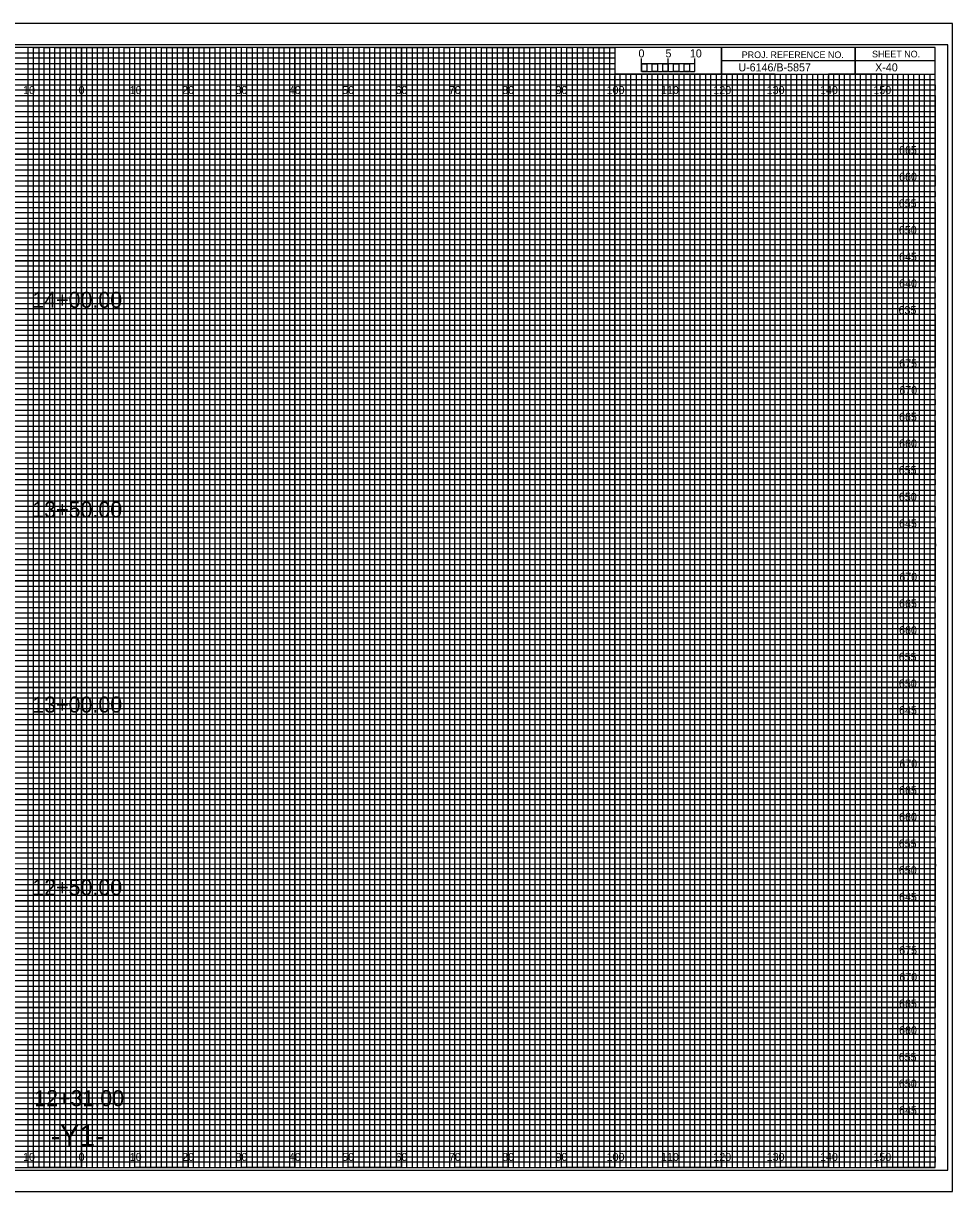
# Model space of a CAD drawing. Extents: x -13 to 323, y 215 to 434.
# Drawn here: x 149.1 to 323.3, y 215.5 to 434.5 of the extents above; entities that cross this region are included whole.
import ezdxf

# ---------------------------------------------------------------- set-up
doc = ezdxf.new("R2010")
doc.units = 0
for name, color, linetype in [('Exist Cross Section Cell', 7, 'Continuous'), ('Exist XS Center Line Elevation Label', 7, 'Continuous'), ('Exist XS Ground Line', 7, 'Continuous'), ('Prop XS Ditch Slope Text', 7, 'Continuous'), ('Prop XS Ditch Standard Text', 7, 'Continuous'), ('Prop XS Dump Level', 7, 'Continuous'), ('Prop XS EOT Tick Mark', 7, 'Continuous'), ('Prop XS Finish Grade', 7, 'Continuous'), ('Prop XS Finish Grade Earthwork', 7, 'Continuous'), ('Prop XS Finish Grade Pavement', 7, 'Continuous'), ('Prop XS Hydro Elevations', 7, 'Continuous'), ('Prop XS Pvmt Edge Slope', 7, 'Continuous'), ('Prop XS SE Text', 7, 'Continuous'), ('Prop XS Side Slope Text', 7, 'Continuous'), ('Prop XS SS Elevation Text', 7, 'Continuous'), ('Prop XS Subgrade Earthwork', 7, 'Continuous'), ('Scratch_Level_3', 7, 'Continuous')]:
    doc.layers.add(name, color=color, linetype=linetype)

msp = doc.modelspace()

# ---------------------------------------------------------------- linework, layer by layer
at = {"layer": 'Exist Cross Section Cell'}
for points in [[(145, 220), (155, 220), (155, 430), (165, 430), (165, 220), (175, 220), (175, 430), (185, 430), (185, 220), (195, 220), (195, 430), (205, 430), (205, 220), (215, 220), (215, 430), (225, 430), (225, 220), (235, 220), (235, 430), (245, 430), (245, 220), (255, 220), (255, 430), (259.93, 430), (260, 430), (260, 425), (264.99, 425), (264.99, 220), (275, 220), (275, 425), (285, 425), (285, 220), (295, 220), (295, 425), (305, 425), (305, 220), (315, 220), (315, 425)], [(0, 425), (275, 425)], [(0, 405), (320, 405), (320, 415), (0, 415)], [(0, 385), (320, 385), (320, 395), (0, 395)], [(0, 365), (320, 365), (320, 375), (0, 375)], [(0, 345), (320, 345), (320, 355), (0, 355)], [(0, 325), (320, 325), (320, 335), (0, 335)], [(0, 305), (320, 305), (320, 315), (0, 315)], [(0, 285), (320, 285), (320, 295), (0, 295)], [(0, 265), (320, 265), (320, 275), (0, 275)], [(0, 245), (320, 245), (320, 255), (0, 255)], [(0, 225), (320, 225), (320, 235), (0, 235)]]:
    msp.add_lwpolyline(points, dxfattribs=at)
at = {"layer": 'Exist XS Center Line Elevation Label'}
for p, q in [((150, 430), (140, 430)), ((150, 220), (150, 430)), ((170, 430), (160, 430)), ((160, 430), (160, 220)), ((170, 220), (170, 430)), ((190, 430), (180, 430)), ((180, 430), (180, 220)), ((190, 220), (190, 430)), ((210, 430), (200, 430)), ((200, 430), (200, 220)), ((210, 220), (210, 430)), ((230, 430), (220, 430)), ((220, 430), (220, 220)), ((230, 220), (230, 430)), ((250, 430), (240, 430)), ((240, 430), (240, 220)), ((250, 220), (250, 430)), ((260, 430), (260, 220)), ((270, 220), (270, 425)), ((290, 425), (280, 425)), ((280, 425), (280, 220)), ((290, 220), (290, 425)), ((310, 425), (300, 425)), ((300, 425), (300, 220)), ((310, 220), (310, 425)), ((160, 220), (150, 220)), ((180, 220), (170, 220)), ((200, 220), (190, 220)), ((220, 220), (210, 220)), ((240, 220), (230, 220)), ((260, 220), (250, 220)), ((280, 220), (270, 220)), ((300, 220), (290, 220)), ((320, 220), (310, 220)), ((320, 220), (320, 220))]:
    msp.add_line(p, q, dxfattribs=at)
for points in [[(0, 420), (320, 420), (320, 410), (0, 410)], [(0, 400), (320, 400), (320, 390), (0, 390)], [(0, 380), (320, 380), (320, 370), (0, 370)], [(0, 360), (320, 360), (320, 350), (0, 350)], [(0, 340), (320, 340), (320, 330), (0, 330)], [(0, 320), (320, 320), (320, 310), (0, 310)], [(0, 300), (320, 300), (320, 290), (0, 290)], [(0, 280), (320, 280), (320, 270), (0, 270)], [(0, 260), (320, 260), (320, 250), (0, 250)], [(0, 240), (320, 240), (320, 230), (0, 230)]]:
    msp.add_lwpolyline(points, dxfattribs=at)
at = {"layer": 'Prop XS Ditch Slope Text'}
msp.add_lwpolyline([(-13.4, 215.5), (323.3, 215.5), (323.3, 434.5), (-13.4, 434.5)], close=True, dxfattribs=at)
at = {"layer": 'Prop XS Ditch Standard Text'}
for p, q in [((265, 425.49), (265, 427.9)), ((265, 426.9), (265, 427.9)), ((270, 425.49), (270, 427.9)), ((275, 425.49), (275, 427.9)), ((275, 426.9), (275, 427.9))]:
    msp.add_line(p, q, dxfattribs=at)
for points in [[(275, 426.9), (265, 426.9), (265, 425.49), (275, 425.49)], [(265, 426.9), (266, 426.9), (266, 425.49), (265, 425.49)], [(267, 426.9), (268, 426.9), (268, 425.49), (267, 425.49)], [(269, 426.9), (270, 426.9), (270, 425.49), (269, 425.49)], [(271, 426.9), (272, 426.9), (272, 425.49), (271, 425.49)], [(273, 426.9), (274, 426.9), (274, 425.49), (273, 425.49)]]:
    msp.add_lwpolyline(points, close=True, dxfattribs=at)
at = {"layer": 'Prop XS Dump Level'}
for p, q in [((305, 430), (305, 425)), ((305, 425), (305, 430)), ((280, 427.5), (280, 425)), ((320, 427.49), (280, 427.49)), ((280, 425), (320, 425))]:
    msp.add_line(p, q, dxfattribs=at)
for points in [[(320, 430), (0, 430), (0, 220), (320, 220)], [(280, 430), (260, 430), (260, 425.03), (280, 425.03)], [(320, 430), (280, 430), (280, 425), (320, 425)]]:
    msp.add_lwpolyline(points, close=True, dxfattribs=at)
at = {"layer": 'Prop XS Finish Grade Earthwork'}
for p, q in [((323.3, 434.5), (-13.4, 434.5)), ((-13.4, 215.5), (323.3, 215.5))]:
    msp.add_line(p, q, dxfattribs=at)
at = {"layer": 'Prop XS SE Text'}
for p, q in [((267, 425), (266.01, 425)), ((266.01, 425), (266.01, 220)), ((267, 220), (267, 425)), ((269, 425), (268, 425)), ((268, 425), (268, 220)), ((269, 220), (269, 425)), ((266.01, 220), (265, 220)), ((268, 220), (267, 220))]:
    msp.add_line(p, q, dxfattribs=at)
for points in [[(150, 220), (151, 220), (151, 430), (152, 430), (152, 220)], [(152, 220), (153, 220), (153, 430), (154, 430), (154, 220)], [(155, 220), (156, 220), (156, 430), (157, 430), (157, 220)], [(157, 220), (158, 220), (158, 430), (159, 430), (159, 220)], [(160, 220), (161, 220), (161, 430), (162, 430), (162, 220)], [(162, 220), (163, 220), (163, 430), (164, 430), (164, 220)], [(165, 220), (166, 220), (166, 430), (167, 430), (167, 220)], [(167, 220), (168, 220), (168, 430), (169, 430), (169, 220)], [(170, 220), (171, 220), (171, 430), (172, 430), (172, 220)], [(172, 220), (173, 220), (173, 430), (174, 430), (174, 220)], [(175, 220), (176, 220), (176, 430), (177, 430), (177, 220)], [(177, 220), (178, 220), (178, 430), (179, 430), (179, 220)], [(180, 220), (181, 220), (181, 430), (182, 430), (182, 220)], [(182, 220), (183, 220), (183, 430), (184, 430), (184, 220)], [(185, 220), (186, 220), (186, 430), (187, 430), (187, 220)], [(187, 220), (188, 220), (188, 430), (189, 430), (189, 220)], [(190, 220), (191, 220), (191, 430), (192, 430), (192, 220)], [(192, 220), (193, 220), (193, 430), (194, 430), (194, 220)], [(195, 220), (196, 220), (196, 430), (197, 430), (197, 220)], [(197, 220), (198, 220), (198, 430), (199, 430), (199, 220)], [(200, 220), (201, 220), (201, 430), (202, 430), (202, 220)], [(202, 220), (203, 220), (203, 430), (204, 430), (204, 220)], [(205, 220), (206, 220), (206, 430), (207, 430), (207, 220)], [(207, 220), (208, 220), (208, 430), (209, 430), (209, 220)], [(210, 220), (211, 220), (211, 430), (212, 430), (212, 220)], [(212, 220), (213, 220), (213, 430), (214, 430), (214, 220)], [(215, 220), (216, 220), (216, 430), (217, 430), (217, 220)], [(217, 220), (218, 220), (218, 430), (219, 430), (219, 220)], [(220, 220), (221, 220), (221, 430), (222, 430), (222, 220)], [(222, 220), (223, 220), (223, 430), (224, 430), (224, 220)], [(225, 220), (226, 220), (226, 430), (227, 430), (227, 220)], [(227, 220), (228, 220), (228, 430), (229, 430), (229, 220)], [(230, 220), (231, 220), (231, 430), (232, 430), (232, 220)], [(232, 220), (233, 220), (233, 430), (234, 430), (234, 220)], [(235, 220), (236, 220), (236, 430), (237, 430), (237, 220)], [(237, 220), (238, 220), (238, 430), (239, 430), (239, 220)], [(240, 220), (241, 220), (241, 430), (242, 430), (242, 220)], [(242, 220), (243, 220), (243, 430), (244, 430), (244, 220)], [(245, 220), (246, 220), (246, 430), (247, 430), (247, 220)], [(247, 220), (248, 220), (248, 430), (249, 430), (249, 220)], [(250, 220), (251, 220), (251, 430), (252, 430), (252, 220)], [(252, 220), (253, 220), (253, 430), (254, 430), (254, 220)], [(255, 220), (256, 220), (256, 430), (257, 430), (257, 220)], [(257, 220), (258, 220), (258, 430), (259, 430), (259, 220)], [(260, 220), (261, 220), (261, 425), (262.02, 425), (262.02, 220)], [(262, 220), (263, 220), (263, 425), (263.99, 425), (263.99, 220)], [(270, 220), (270.98, 220), (270.98, 425), (272, 425), (272, 220)], [(272, 220), (273, 220), (273, 425), (274.05, 425), (274.05, 220)], [(275, 220), (276, 220), (276, 425), (277, 425), (277, 220)], [(277, 220), (278, 220), (278, 425), (279, 425), (279, 220)], [(280, 220), (281, 220), (281, 425), (282, 425), (282, 220)], [(282, 220), (283, 220), (283, 425), (284, 425), (284, 220)], [(285, 220), (286, 220), (286, 425), (287, 425), (287, 220)], [(287, 220), (288, 220), (288, 425), (289, 425), (289, 220)], [(290, 220), (291, 220), (291, 425), (292, 425), (292, 220)], [(292, 220), (293, 220), (293, 425), (294, 425), (294, 220)], [(295, 220), (296, 220), (296, 425), (297, 425), (297, 220)], [(297, 220), (298, 220), (298, 425), (299, 425), (299, 220)], [(300, 220), (301, 220), (301, 425), (302, 425), (302, 220)], [(302, 220), (303, 220), (303, 425), (304, 425), (304, 220)], [(305, 220), (306, 220), (306, 425), (307, 425), (307, 220)], [(307, 220), (308, 220), (308, 425), (309, 425), (309, 220)], [(310, 220), (311, 220), (311, 425), (312, 425), (312, 220)], [(312, 220), (313, 220), (313, 425), (314, 425), (314, 220)], [(315, 220), (316, 220), (316, 425), (317, 425), (317, 220)], [(317, 220), (318, 220), (318, 425), (319, 425), (319, 220)]]:
    msp.add_lwpolyline(points, dxfattribs=at)
at = {"layer": 'Prop XS Side Slope Text'}
msp.add_lwpolyline([(-10.8, 219.5), (322.4, 219.5), (322.4, 430.5), (-10.8, 430.5)], close=True, dxfattribs=at)
at = {"layer": 'Prop XS SS Elevation Text'}
for p, q in [((150, 220), (150, 430)), ((160, 220), (160, 430)), ((170, 220), (170, 430)), ((180, 220), (180, 430)), ((190, 220), (190, 430)), ((200, 220), (200, 430)), ((210, 220), (210, 430)), ((220, 220), (220, 430)), ((230, 220), (230, 430)), ((240, 220), (240, 430)), ((250, 220), (250, 430)), ((260, 220), (260, 424.69)), ((270, 220), (270, 424.69)), ((280, 220), (280, 424.69)), ((290, 220), (290, 424.69)), ((300, 220), (300, 424.69)), ((310, 220), (310, 424.69)), ((0, 420), (320, 420)), ((0, 410), (320, 410)), ((0, 400), (320, 400)), ((0, 390), (320, 390)), ((0, 380), (320, 380)), ((0, 370), (320, 370)), ((0, 360), (320, 360)), ((0, 350), (320, 350)), ((0, 340), (320, 340)), ((0, 330), (320, 330)), ((0, 320), (320, 320)), ((0, 310), (320, 310)), ((0, 300), (320, 300)), ((0, 290), (320, 290)), ((0, 280), (320, 280)), ((0, 270), (320, 270)), ((0, 260), (320, 260)), ((0, 250), (320, 250)), ((0, 240), (320, 240)), ((0, 230), (320, 230))]:
    msp.add_line(p, q, dxfattribs=at)
at = {"layer": 'Scratch_Level_3'}
for p, q in [((0, 429), (260, 429)), ((260, 427.98), (0, 427.98)), ((260, 429), (260, 427.98)), ((0, 427), (260, 427)), ((260, 425.89), (0, 425.89)), ((260, 427), (260, 425.89)), ((0, 424), (320, 424))]:
    msp.add_line(p, q, dxfattribs=at)
for points in [[(0, 423), (270, 423), (320, 423), (320, 422), (0, 422)], [(0, 421), (320, 421), (320, 419), (0, 419)], [(0, 418), (320, 418), (320, 417), (0, 416.98)], [(0, 416), (320, 416), (320, 414), (0, 414)], [(0, 413), (320, 413), (320, 412), (0, 412)], [(0, 411), (320, 411), (320, 409), (0, 409)], [(0, 408), (320, 408), (320, 407), (0, 407)], [(0, 406), (320, 406), (320, 404), (0, 404)], [(0, 403), (320, 403), (320, 402), (0, 402)], [(0, 401), (320, 401), (320, 399), (0, 399)], [(0, 398), (320, 398), (320, 397), (0, 397)], [(0, 396), (320, 396), (320, 393.95), (320, 393), (320, 392), (0, 392)], [(0, 394), (320, 394), (320, 393), (0, 393)], [(0, 391), (320, 391), (320, 389), (0, 389.03)], [(0, 389.03), (320, 389), (320, 388), (0, 388)], [(0, 387), (320, 387), (320, 386), (0, 386)], [(0, 384), (320, 384), (320, 383), (0, 383)], [(0, 382), (320, 382), (320, 381), (0, 381)], [(-0.07, 378.89), (320, 378.89), (320, 377.88), (-0.07, 377.88)], [(0, 377), (320, 377), (320, 376), (0, 376)], [(0, 374), (320, 374), (320, 373), (0, 373)], [(0, 372), (320, 372), (320, 371), (0, 371)], [(0, 369), (320, 369), (320, 368), (0, 368)], [(0, 367), (320, 367), (320, 366), (0, 366)], [(0, 364), (320, 364), (320, 363), (0, 363)], [(0, 362), (320, 362), (320, 361), (0, 361)], [(0, 359), (320, 359), (319.99, 357.98), (0, 358)], [(0, 357), (320, 357), (320, 356), (0, 356)], [(0, 354), (320, 354), (320, 353), (0, 353)], [(0, 352), (320, 352), (320, 351), (0, 351)], [(0, 349), (320, 349), (320, 348), (0, 348)], [(0, 347), (320, 347), (320, 346), (0, 346)], [(0, 344), (320, 344), (320, 343), (0, 343)], [(0, 342), (320, 342), (320, 341), (0, 341)], [(0, 339), (320, 339), (320, 338), (0, 338)], [(0, 336.99), (320.07, 336.91), (320, 336), (0, 336)], [(0, 334), (320, 334), (320, 333), (0, 333)], [(0, 332), (320, 332), (320, 331), (0, 331)], [(0, 329), (320, 329), (320, 328), (0, 328)], [(0, 327), (320, 327), (320, 326), (0, 326)], [(0, 324), (320, 324), (320, 323), (0, 323)], [(0, 322), (320, 322), (320, 321), (0, 321)], [(0, 319), (320, 319), (320, 318), (0, 318)], [(0, 317), (320, 317), (320, 316), (0, 316)], [(0, 314), (320, 314), (320, 313), (0, 313)], [(0, 312), (320, 312), (320, 311), (0, 311)], [(0, 309), (320, 309), (320, 308), (0, 308)], [(0, 307), (320, 307), (320, 306), (0, 306)], [(0, 304), (320, 304), (320, 303), (0, 303)], [(0, 302), (320, 302), (320, 301), (0, 301)], [(0, 299), (320, 299), (319.99, 297.98), (0, 298)], [(0, 297), (320, 297), (320, 296), (0, 296)], [(0, 294), (320, 294), (320, 293), (0, 293)], [(0, 292), (320, 292), (320, 291), (0, 291)], [(0, 289), (320, 289), (320, 288), (0, 288)], [(0, 287), (320, 287), (320, 286), (0, 286)], [(0, 284), (320, 284), (320, 283), (0, 283)], [(0, 282), (320, 282), (320, 281), (0, 281)], [(0, 279), (320, 279), (320, 278), (0, 278)], [(0, 276.99), (320.07, 276.91), (320, 276), (0, 276)], [(0, 274), (320, 274), (320, 273), (0, 273)], [(0, 272), (320, 272), (320, 271), (0, 271)], [(0, 269), (320, 269), (320, 268), (0, 268)], [(0, 267), (320, 267), (320, 266), (0, 266)], [(0, 264), (320, 264), (320, 263), (0, 263)], [(0, 262), (320, 262), (320, 261), (0, 261)], [(0, 259), (320, 259), (320, 258), (0, 258)], [(0, 257), (320, 257), (320, 256), (0, 256)], [(0, 254), (320, 254), (320, 253), (0, 253)], [(0, 252), (320, 252), (320, 251), (0, 251)], [(0, 249), (320, 249), (320, 248), (0, 248)], [(0, 247), (320, 247), (320, 246), (0, 246)], [(0, 244), (320, 244), (320, 243), (0, 243)], [(0, 242), (320, 242), (320, 241), (0, 241)], [(0, 239), (320, 239), (320, 238), (0, 238)], [(0, 237), (320, 237), (320, 236), (0, 236)], [(0, 234), (320, 234), (320, 233), (0, 233)], [(0, 232), (320, 232), (320, 231), (0, 231)], [(0, 229), (320, 229), (320, 228), (0, 228)], [(0, 227), (320, 227), (320, 226), (0, 226)], [(0, 224), (320, 224), (320, 223), (0, 223)], [(0, 222), (320, 222), (320, 221), (0, 221)]]:
    msp.add_lwpolyline(points, dxfattribs=at)

# ---------------------------------------------------------------- texts
at = {"layer": 'Exist XS Ground Line'}
for s, p in [('10', (149.04, 421.25)), ('0', (159.45, 421.25)), ('0', (159.45, 421.25)), ('10', (169.04, 421.25)), ('20', (178.86, 421.25)), ('30', (188.86, 421.25)), ('40', (198.86, 421.25)), ('50', (208.86, 421.25)), ('60', (218.86, 421.25)), ('70', (228.86, 421.25)), ('80', (238.86, 421.25)), ('90', (248.86, 421.25)), ('100', (258.44, 421.25)), ('110', (268.62, 421.25)), ('120', (278.44, 421.25)), ('130', (288.44, 421.25)), ('140', (298.44, 421.25)), ('150', (308.44, 421.25)), ('10', (149.04, 221.25)), ('0', (159.45, 221.25)), ('0', (159.45, 221.25)), ('10', (169.04, 221.25)), ('20', (178.86, 221.25)), ('30', (188.86, 221.25)), ('40', (198.86, 221.25)), ('50', (208.86, 221.25)), ('60', (218.86, 221.25)), ('70', (228.86, 221.25)), ('80', (238.86, 221.25)), ('90', (248.86, 221.25)), ('100', (258.44, 221.25)), ('110', (268.62, 221.25)), ('120', (278.44, 221.25)), ('130', (288.44, 221.25)), ('140', (298.44, 221.25)), ('150', (308.44, 221.25))]:
    msp.add_text(s, height=1.5, dxfattribs=at).set_placement(p)
at = {"layer": 'Prop XS Ditch Standard Text'}
msp.add_text('0', height=1.5, dxfattribs=at).set_placement((264.41, 428.12))
at = {"layer": 'Prop XS Dump Level'}
for s, p in [('PROJ. REFERENCE NO.', (283.77, 427.99)), ('SHEET NO.', (308.19, 428.12))]:
    msp.add_text(s, height=1.25, dxfattribs=at).set_placement(p)
at = {"layer": 'Prop XS EOT Tick Mark'}
msp.add_text('U-6146/B-5857', height=1.5, dxfattribs=at).set_placement((283.13, 425.5))
at = {"layer": 'Prop XS Finish Grade'}
for s, p in [('665', (313.25, 410)), ('660', (313.26, 405)), ('655', (313.2, 400)), ('650', (313.22, 395)), ('645', (313.25, 390)), ('640', (313.26, 385)), ('635', (313.16, 380)), ('675', (313.28, 370)), ('670', (313.3, 365)), ('665', (313.25, 360)), ('660', (313.26, 355)), ('655', (313.2, 350)), ('650', (313.22, 345)), ('645', (313.25, 340)), ('670', (313.3, 330)), ('665', (313.25, 325)), ('660', (313.26, 320)), ('655', (313.2, 315)), ('650', (313.22, 310)), ('645', (313.25, 305)), ('670', (313.3, 295)), ('665', (313.25, 290)), ('660', (313.26, 285)), ('655', (313.2, 280)), ('650', (313.22, 275)), ('645', (313.25, 270)), ('675', (313.28, 260)), ('670', (313.3, 255)), ('665', (313.25, 250)), ('660', (313.26, 245)), ('655', (313.2, 240)), ('650', (313.22, 235)), ('645', (313.25, 230))]:
    msp.add_text(s, height=1.5, dxfattribs=at).set_placement(p)
at = {"layer": 'Prop XS Finish Grade Pavement'}
msp.add_text('-Y1-', height=4, dxfattribs=at).set_placement((154.21, 224))
at = {"layer": 'Prop XS Hydro Elevations'}
for s, p in [('5', (269.47, 428.12)), ('10', (274.04, 428.12))]:
    msp.add_text(s, height=1.5, dxfattribs=at).set_placement(p)
at = {"layer": 'Prop XS Pvmt Edge Slope'}
msp.add_text('X-40', height=1.5, dxfattribs=at).set_placement((308.77, 425.5))
at = {"layer": 'Prop XS Subgrade Earthwork'}
for s, p in [('14+00.00', (150.77, 381.18)), ('13+50.00', (150.77, 341.87)), ('13+00.00', (150.77, 305.3)), ('12+50.00', (150.77, 271.05)), ('12+31.00', (151.13, 231.52))]:
    msp.add_text(s, height=3, dxfattribs=at).set_placement(p)

doc.saveas('drawing.dxf')
